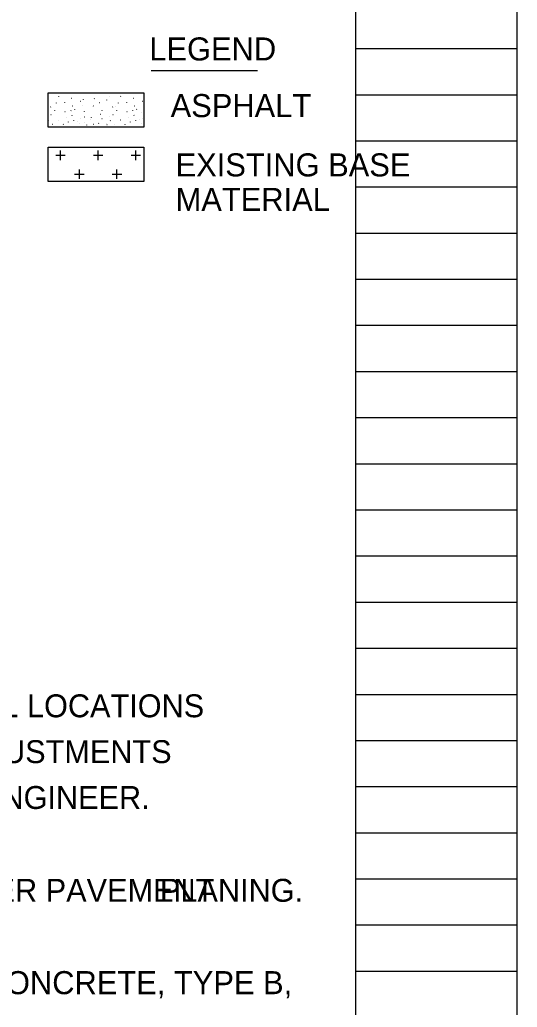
# Model space of a CAD drawing. Extents: x 0 to 34, y -1.4 to 22.
# Drawn here: x 21.64 to 24.66, y 10.28 to 16.27 of the extents above; entities that cross this region are included whole.
import ezdxf

# ---------------------------------------------------------------- set-up
doc = ezdxf.new("R2010")
doc.units = 0
doc.layers.add('SH_Data', color=7, linetype='Continuous')
doc.layers.add('SH_Text', color=7, linetype='Continuous')

msp = doc.modelspace()

# ---------------------------------------------------------------- linework, layer by layer
at = {"layer": 'SH_Data'}
for p, q in [((23.68, 0.98), (23.68, 21.14)), ((24.66, 0.98), (24.66, 21.14)), ((23.68, 16.1), (24.66, 16.1)), ((23.68, 15.82), (24.66, 15.82)), ((23.68, 15.54), (24.66, 15.54)), ((23.68, 15.26), (24.66, 15.26)), ((23.68, 14.98), (24.66, 14.98)), ((23.68, 14.7), (24.66, 14.7)), ((23.68, 14.42), (24.66, 14.42)), ((23.68, 14.14), (24.66, 14.14)), ((23.68, 13.86), (24.66, 13.86)), ((23.68, 13.58), (24.66, 13.58)), ((23.68, 13.3), (24.66, 13.3)), ((23.68, 13.02), (24.66, 13.02)), ((23.68, 12.74), (24.66, 12.74)), ((23.68, 12.46), (24.66, 12.46)), ((23.68, 12.18), (24.66, 12.18)), ((23.68, 11.9), (24.66, 11.9)), ((23.68, 11.62), (24.66, 11.62)), ((23.68, 11.34), (24.66, 11.34)), ((23.68, 11.06), (24.66, 11.06)), ((23.68, 10.78), (24.66, 10.78)), ((23.68, 10.5), (24.66, 10.5))]:
    msp.add_line(p, q, dxfattribs=at)
at = {"layer": 'SH_Text'}
for p, q in [((22.4384, 15.966), (23.0846, 15.966)), ((21.8644, 15.769), (21.8634, 15.7698)), ((21.8776, 15.8093), (21.8781, 15.8113)), ((21.9141, 15.7713), (21.9146, 15.773)), ((21.9564, 15.7963), (21.9554, 15.7972)), ((22.0103, 15.7795), (22.0083, 15.7785)), ((22.0288, 15.7912), (22.0278, 15.7923)), ((22.0931, 15.7947), (22.0938, 15.7968)), ((22.1271, 15.771), (22.1251, 15.7707)), ((22.1644, 15.788), (22.1644, 15.788)), ((22.1688, 15.7875), (22.1694, 15.7895)), ((22.1848, 15.8113), (22.1848, 15.8113)), ((22.2403, 15.769), (22.2393, 15.7698)), ((22.2533, 15.8093), (22.2541, 15.8113)), ((22.2898, 15.7713), (22.2906, 15.773)), ((22.3324, 15.7963), (22.3314, 15.7972)), ((22.3861, 15.7795), (22.3841, 15.7785)), ((21.8284, 15.7448), (21.8289, 15.7465)), ((21.8539, 15.724), (21.8544, 15.7258)), ((21.9168, 15.7165), (21.9149, 15.716)), ((21.9513, 15.7212), (21.9521, 15.7232)), ((21.9633, 15.751), (21.9613, 15.7505)), ((21.9743, 15.7298), (21.9748, 15.7317)), ((22.0219, 15.752), (22.0211, 15.7532)), ((22.0329, 15.7185), (22.0336, 15.7203)), ((22.0883, 15.7508), (22.0873, 15.7518)), ((22.1413, 15.724), (22.1421, 15.7258)), ((22.2041, 15.7448), (22.2049, 15.7465)), ((22.2246, 15.7495), (22.2246, 15.7495)), ((22.2299, 15.724), (22.2304, 15.7258)), ((22.2926, 15.7165), (22.2908, 15.716)), ((22.3271, 15.7212), (22.3279, 15.7232)), ((22.3391, 15.751), (22.3371, 15.7505)), ((22.3501, 15.7298), (22.3506, 15.7317)), ((22.3779, 15.7098), (22.3779, 15.7098)), ((21.8153, 15.6613), (21.8143, 15.6623)), ((21.8313, 15.6983), (21.8294, 15.6978)), ((21.8764, 15.6653), (21.8754, 15.6663)), ((21.9231, 15.6805), (21.9236, 15.6822)), ((21.9368, 15.6522), (21.9374, 15.6542)), ((21.9591, 15.6943), (21.9581, 15.6955)), ((21.9688, 15.6623), (21.9693, 15.6643)), ((21.9938, 15.6593), (21.9938, 15.6593)), ((22.0103, 15.673), (22.0093, 15.6742)), ((22.0328, 15.6527), (22.0316, 15.6537)), ((22.0341, 15.6837), (22.0321, 15.6833)), ((22.0681, 15.6692), (22.0681, 15.6692)), ((22.0768, 15.6822), (22.0773, 15.684)), ((22.1208, 15.6458), (22.1198, 15.6467)), ((22.1334, 15.7003), (22.1314, 15.6997)), ((22.1406, 15.6738), (22.1388, 15.6733)), ((22.1841, 15.6847), (22.1841, 15.6847)), ((22.1913, 15.6613), (22.1903, 15.6623)), ((22.2071, 15.6983), (22.2051, 15.6978)), ((22.2523, 15.6653), (22.2513, 15.6663)), ((22.2989, 15.6805), (22.2996, 15.6822)), ((22.3126, 15.6522), (22.3134, 15.6542)), ((22.3351, 15.6943), (22.3339, 15.6955)), ((22.3446, 15.6623), (22.3451, 15.6643)), ((22.3659, 15.6683), (22.3659, 15.6683)), ((22.3861, 15.673), (22.3851, 15.6742)), ((21.8389, 15.6388), (21.8379, 15.64)), ((21.9049, 15.6385), (21.9058, 15.6405)), ((21.9878, 15.6253), (21.9886, 15.6248)), ((21.9886, 15.6248), (21.9891, 15.6243)), ((22.0043, 15.6428), (22.0033, 15.6438)), ((22.0484, 15.635), (22.0474, 15.636)), ((22.0876, 15.6388), (22.0864, 15.64)), ((22.1674, 15.643), (22.1674, 15.643)), ((22.1716, 15.637), (22.1698, 15.636)), ((22.2148, 15.6388), (22.2138, 15.64)), ((22.2808, 15.6385), (22.2816, 15.6405)), ((22.3636, 15.6253), (22.3644, 15.6248)), ((22.3644, 15.6248), (22.3649, 15.6243)), ((22.3801, 15.6428), (22.3791, 15.6438)), ((21.8883, 15.4235), (21.8883, 15.4807)), ((22.1168, 15.4235), (22.1168, 15.4807)), ((22.3451, 15.4235), (22.3451, 15.4807)), ((21.8599, 15.4522), (21.9169, 15.4522)), ((22.0883, 15.4522), (22.1451, 15.4522)), ((22.3164, 15.4522), (22.3736, 15.4522)), ((22.0026, 15.3093), (22.0026, 15.3665)), ((22.2308, 15.3093), (22.2308, 15.3665)), ((21.9739, 15.3378), (22.0311, 15.3378)), ((22.2024, 15.3378), (22.2596, 15.3378))]:
    msp.add_line(p, q, dxfattribs=at)
for points in [[(21.8133, 15.8322), (22.3934, 15.8322), (22.3934, 15.623), (21.8133, 15.623)], [(21.8133, 15.5015), (22.3934, 15.5015), (22.3934, 15.2922), (21.8133, 15.2922)]]:
    msp.add_lwpolyline(points, close=True, dxfattribs=at)

# ---------------------------------------------------------------- texts
for s, height, p in [('LEGEND', 0.14, (22.4272, 16.0276)), ('ASPHALT', 0.14, (22.5566, 15.6836)), ('EXISTING BASE', 0.14, (22.5867, 15.3239)), ('MATERIAL', 0.14, (22.5867, 15.1139)), ('NOTE:  THE ENGINEER SHALL FIELD VERIFY ALL LOCATIONS', 0.139111, (17.24, 12.0409)), ('PRIOR TO THE BEGINNING OF WORK.  ANY ADJUSTMENTS', 0.139111, (17.24, 11.7627)), ('NECESSARY SHALL BE AS DIRECTED BY THE ENGINEER.', 0.139111, (17.24, 11.4844)), ('THE PAVEMENT REPAIRS SHALL BE DONE AFTER PAVEMENT ', 0.139111, (17.24, 10.9209)), ('PLANING.', 0.13911, (22.4919, 10.9209)), ('ITEM 424 - FINE GRADED POLYMER ASPHALT CONCRETE, TYPE B, ', 0.14, (17.24, 10.36))]:
    msp.add_text(s, height=height, dxfattribs=at).set_placement(p)

doc.saveas('drawing.dxf')
